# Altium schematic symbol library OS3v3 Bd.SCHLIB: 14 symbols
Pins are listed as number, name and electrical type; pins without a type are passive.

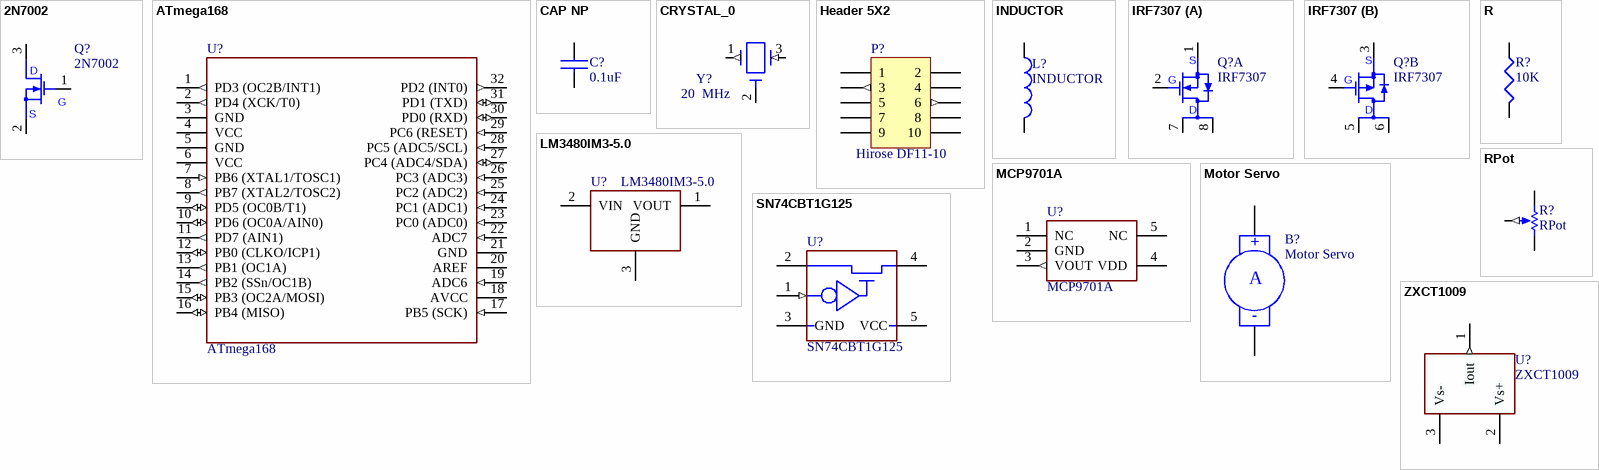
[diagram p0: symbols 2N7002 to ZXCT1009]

## 2N7002
designator Q?
N FET; Manufacturer: Diodes Inc.; Vendor: DigiKey; Vendor P/N: 2N7002-FDICT-ND; Item Description: FET, N, 60V, 115mA, Vgs 2.5V, SOT23
footprint SOT23-3
pins: 1 G, 2 S, 3 D

## ATmega168
designator U?
Manufacturer: Atmel; Item Description: IC, Microprocessor, ATmega168; Mfg. P/N: ATMEGA168-20AU; Vendor: DigiKey; Vendor P/N: ATMEGA168-20AU-ND
footprint 32M1-A_N (QFN, 32-Leads, Body 5x5mm, Pitch 0.5mm, IPC Medium Density)
pins: 1 PD3 (OC2B/INT1) (out), 2 PD4 (XCK/T0) (out), 3 GND (power), 4 VCC (power), 5 GND (power), 6 VCC (power), 7 PB6 (XTAL1/TOSC1) (in), 8 PB7 (XTAL2/TOSC2) (out), 9 PD5 (OC0B/T1) (io), 10 PD6 (OC0A/AIN0) (io), 11 PD7 (AIN1) (out), 12 PB0 (CLKO/ICP1) (io), 13 PB1 (OC1A) (out), 14 PB2 (SSn/OC1B) (out), 15 PB3 (OC2A/MOSI) (io), 16 PB4 (MISO) (io), 17 PB5 (SCK) (in), 18 AVCC (power), 19 ADC6 (in), 20 AREF (power), 21 GND (power), 22 ADC7 (in), 23 PC0 (ADC0) (in), 24 PC1 (ADC1) (in), 25 PC2 (ADC2) (in), 26 PC3 (ADC3) (in), 27 PC4 (ADC4/SDA) (io), 28 PC5 (ADC5/SCL) (in), 29 PC6 (RESET) (in), 30 PD0 (RXD) (io), 31 PD1 (TXD) (io), 32 PD2 (INT0) (out)

## CAP NP
designator C?, comment 0.1uF
Manufacturer: Panasonic; Vendor: DigiKey; Vendor P/N: PCC1762CT-ND; Item Description: Capacitor, 0.1uF, X7R, ±10%, 16V, Ceramic, SM, 0603; Mfg. P/N: ECJ-1VB1C104K
footprint C0603
pins: 1, 2

## CRYSTAL_0
designator Y?, comment 20  MHz
Manufacturer: TDK; Item Description: Resionator, Ceramic, 20MHz., 0.5%; Mfg. P/N: CCR20.0MXC7T; Vendor: DigiKey; Vendor P/N: 445-1649-1-ND
footprint MXC7T (TDK Ceramic Resonator)
pins: 1 (out), 2 (power), 3 (in)

## Header 5X2
designator P?, comment Hirose DF11-10
Header, 5-Pin, Dual row; Manufacturer: Molex; Item Description: Connector, TH, 2mm, 2x10; Mfg. P/N: 87831-1020; Vendor: DigiKey; Vendor P/N: WM18560-ND
footprint FD11-10E (Hirose 2mm, 10 pin, TH, Edge Application)
pins: 1, 2, 3 (out), 4, 5, 6 (out), 7, 8, 9, 10

## INDUCTOR
designator L?
Manufacturer: TDK; Item Description: Inductor, 10uH, 3mA, 10%; Mfg. P/N: MLF1608E100K; Vendor: DigiKey; Vendor P/N: 445-1025-1-ND
footprint C0603
pins: 1, 2

## IRF7307
designator Q?
Manufacturer: IRF; Item Description: MOSFET, Dual, N/P, 20/-20V, 4.3/-3.4A; Mfg. P/N: IRF7307TRPBF; Vendor: DigiKey; Vendor P/N: IRF7307PBFCT-ND
footprint SO8
part A pins: 1 S, 2 G, 7 D, 8 D
part B pins: 3 S, 4 G, 5 D, 6 D

## LM3480IM3-5.0
designator U?
Manufacturer: National; Item Description: IC, Voltaage Regulator, 5V, 100mA. 1.2V DO; Mfg. P/N: LM3480IM3-5.0/NOPB; Vendor: DigiKey; Vendor P/N: LM3480IM3-5.0CT-ND
footprint SOT23-3
pins: 1 VOUT (power), 2 VIN (power), 3 GND (power)

## MCP9701A
designator U?
Manufacturer: Microchip; Item Description: IC, Thermal Sensor, 19.5mV/C; Mfg. P/N: MCP9701AT-E/LT; Vendor: DigiKey; Vendor P/N: MCP9701AT-E/LTCT-ND
footprint SC70 -5
pins: 1 NC, 2 GND (power), 3 VOUT (out), 4 VDD (power), 5 NC

## Motor Servo
designator B?  (no BOM)
Servo Motor
footprint Servo Pads
pins: 1 +, 2 -

## R
designator R?, comment 10K
Manufacturer: Panasonic; Vendor: DigiKey; Vendor P/N: P10KGCT-ND; Item Description: Resistor, CF, 10K Ohms, 5%, 0.1W, SM, 0603; Mfg. P/N: ERJ-3GEYJ103V
footprint R0603
footprint R0402
footprint R1206
footprint R1812
footprint R2512
pins: 1, 2

## RPot
designator R?  (no BOM)
Potentiometer; Item Description: Servo Pot
pins: 1 TOP, 2 BOT, 3 TAP (out)
1 alternate drawing of the same symbol

## SN74CBT1G125
designator U?
Manufacturer: TI; Item Description: IC, FET Bus Switch, Single; Mfg. P/N: SN74CBT1G125DCKR; Vendor: DigiKey; Vendor P/N: 296-6410-1-ND
footprint SC70 -5
pins: 1 OEn (in), 2 A, 3 GND, 4 B, 5 VCC

## ZXCT1009
designator U?
Manufacturer: ZETEX; Item Description: IC, HS Current Monitor, 20V, 10mA/V; Mfg. P/N: ZXCT1009FTA; Vendor: DigiKey; Vendor P/N: ZXCT1009FCT-ND
footprint SOT23-3F (Zetex cw pin numbers)
pins: 1 Iout (out), 2 Vs+, 3 Vs-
